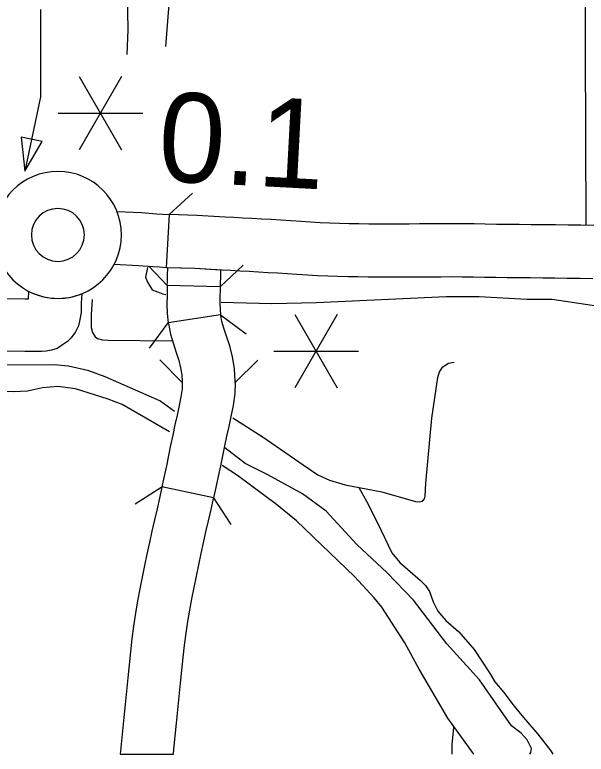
# Model space of a CAD drawing. Extents: x 1370130 to 1380143, y 377636 to 380256.
# Drawn here: x 1378668.8 to 1378782.2, y 377905.2 to 378052.1 of the extents above; entities that cross this region are included whole.
import ezdxf

# ---------------------------------------------------------------- set-up
doc = ezdxf.new("R2010")
doc.units = 0
for name, color, linetype in [('Level 10', 7, 'Continuous'), ('Level 15', 7, 'Continuous'), ('Level 24', 7, 'Continuous'), ('Level 33', 7, 'Continuous'), ('Level 34', 7, 'Continuous'), ('Level 35', 7, 'Continuous'), ('Level 37', 7, 'Continuous'), ('Level 48', 7, 'Continuous'), ('Level 6', 7, 'Continuous')]:
    doc.layers.add(name, color=color, linetype=linetype)

msp = doc.modelspace()

# ---------------------------------------------------------------- linework, layer by layer
at = {"layer": 'Level 10'}
for p, q in [((1378709.54, 377998.02), (1378699.04, 377998.3)), ((1378709.63, 377992.45), (1378699.24, 377990.91)), ((1378697.96, 377958.26), (1378697.48, 377956.09)), ((1378697.98, 377958.34), (1378697.96, 377958.26)), ((1378708.24, 377956.12), (1378697.98, 377958.34)), ((1378697.48, 377956.09), (1378697, 377953.93)), ((1378707.73, 377953.81), (1378708.22, 377956.03)), ((1378708.22, 377956.03), (1378708.24, 377956.12)), ((1378697, 377953.93), (1378696.49, 377951.75)), ((1378707.23, 377951.59), (1378707.73, 377953.81)), ((1378696.49, 377951.75), (1378695.97, 377949.51)), ((1378706.72, 377949.38), (1378707.23, 377951.59)), ((1378695.97, 377949.51), (1378695.48, 377947.24)), ((1378706.22, 377947.21), (1378706.72, 377949.38)), ((1378695.48, 377947.24), (1378695.01, 377944.97)), ((1378705.75, 377945.05), (1378706.22, 377947.21)), ((1378695.01, 377944.97), (1378694.53, 377942.7)), ((1378705.29, 377942.83), (1378705.75, 377945.05)), ((1378694.53, 377942.7), (1378694.07, 377940.41)), ((1378704.82, 377940.58), (1378705.29, 377942.83)), ((1378694.07, 377940.41), (1378693.6, 377938.07)), ((1378704.36, 377938.32), (1378704.82, 377940.58)), ((1378693.6, 377938.07), (1378693.15, 377935.67)), ((1378703.91, 377936.07), (1378704.36, 377938.32)), ((1378703.49, 377933.83), (1378703.91, 377936.07)), ((1378693.15, 377935.67), (1378692.73, 377933.21)), ((1378692.73, 377933.21), (1378692.36, 377930.68)), ((1378703.1, 377931.56), (1378703.49, 377933.83)), ((1378702.76, 377929.26), (1378703.1, 377931.56)), ((1378692.36, 377930.68), (1378692.03, 377928.11)), ((1378702.46, 377926.89), (1378702.76, 377929.26)), ((1378692.03, 377928.11), (1378691.76, 377925.54)), ((1378702.2, 377924.42), (1378702.46, 377926.89)), ((1378691.76, 377925.54), (1378691.48, 377922.97)), ((1378701.93, 377921.88), (1378702.2, 377924.42)), ((1378691.48, 377922.97), (1378691.22, 377920.36)), ((1378701.66, 377919.3), (1378701.93, 377921.88)), ((1378691.22, 377920.36), (1378690.95, 377917.74)), ((1378701.4, 377916.71), (1378701.66, 377919.3)), ((1378690.95, 377917.74), (1378690.7, 377915.1)), ((1378701.15, 377914.05), (1378701.4, 377916.71)), ((1378690.7, 377915.1), (1378690.43, 377912.5)), ((1378700.87, 377911.39), (1378701.15, 377914.05)), ((1378690.43, 377912.5), (1378690.14, 377909.87)), ((1378700.59, 377908.8), (1378700.87, 377911.39)), ((1378690.14, 377909.87), (1378689.89, 377907.24)), ((1378700.34, 377906.23), (1378700.59, 377908.8)), ((1378689.89, 377907.24), (1378689.7, 377905.22)), ((1378689.7, 377905.22), (1378700.24, 377905.22)), ((1378700.24, 377905.22), (1378700.34, 377906.23))]:
    msp.add_line(p, q, dxfattribs=at)
for points in [[(1378699.04, 377998.3), (1378699.06, 377999.07), (1378699.09, 378000.31), (1378699.13, 378001.9), (1378704.49, 378001.73)], [(1378704.49, 378001.73), (1378709.63, 378001.44), (1378709.62, 378001.15), (1378709.59, 378000.04), (1378709.56, 377998.79), (1378709.54, 377998.02)], [(1378699.04, 377998.3), (1378699.04, 377998.16), (1378699.02, 377997.74), (1378698.99, 377996.29), (1378698.96, 377994.64), (1378699.03, 377992.76), (1378699.24, 377990.91)], [(1378709.54, 377998.02), (1378709.53, 377997.83), (1378709.52, 377997.46), (1378709.48, 377996.09), (1378709.47, 377994.77), (1378709.51, 377993.55), (1378709.63, 377992.45)], [(1378712.52, 377979.03), (1378712.53, 377979.35), (1378712.35, 377981.82), (1378711.96, 377984.14), (1378711.42, 377986.29), (1378710.82, 377988.22), (1378710.27, 377989.84), (1378709.88, 377991.17), (1378709.64, 377992.37), (1378709.63, 377992.45)], [(1378699.24, 377990.91), (1378699.26, 377990.74), (1378699.68, 377988.66), (1378700.25, 377986.7), (1378700.83, 377984.97), (1378701.31, 377983.44), (1378701.68, 377981.98), (1378701.92, 377980.57), (1378702.01, 377979.18), (1378702.01, 377979.07)], [(1378702.01, 377979.07), (1378701.96, 377977.77), (1378701.74, 377976.21), (1378701.4, 377974.47), (1378700.98, 377972.58), (1378700.54, 377970.61), (1378700.11, 377968.61), (1378699.69, 377966.59), (1378699.28, 377964.56), (1378698.87, 377962.51), (1378698.42, 377960.42), (1378697.98, 377958.34)], [(1378712.51, 377979.03), (1378712.51, 377978.95), (1378712.43, 377976.84), (1378712.1, 377974.46), (1378711.67, 377972.3), (1378711.23, 377970.3), (1378710.79, 377968.37), (1378710.38, 377966.45), (1378709.98, 377964.5), (1378709.58, 377962.48), (1378709.15, 377960.38), (1378708.69, 377958.22), (1378708.24, 377956.12)]]:
    msp.add_lwpolyline(points, dxfattribs=at)
at = {"layer": 'Level 15'}
for points in [[(1378689.04, 378013.01), (1378693.93, 378012.77), (1378696.9, 378012.56), (1378699.38, 378012.4)], [(1378699.38, 378012.4), (1378698.84, 378001.91), (1378704.49, 378001.73), (1378709.96, 378001.42), (1378711.65, 378001.33), (1378713.45, 378001.21), (1378715.29, 378001.12), (1378717.14, 378001.02), (1378719.04, 378000.91), (1378720.95, 378000.8), (1378722.87, 378000.67), (1378724.84, 378000.53), (1378726.86, 378000.4), (1378728.86, 378000.3), (1378730.87, 378000.21), (1378732.87, 378000.14), (1378734.9, 378000.08), (1378736.85, 378000.06), (1378738.92, 378000.01), (1378740.96, 378000.01), (1378742.98, 378000), (1378745, 378000.01), (1378747.07, 378000.01), (1378749.2, 378000.02), (1378751.25, 378000.04), (1378753.37, 378000.05), (1378755.46, 378000.08), (1378757.58, 378000.05), (1378759.76, 378000.03), (1378761.96, 377999.98), (1378764.21, 377999.95), (1378766.49, 377999.92), (1378768.8, 377999.9), (1378771.13, 377999.88), (1378773.54, 377999.85), (1378775.94, 377999.84), (1378778.42, 377999.78), (1378780.95, 377999.76), (1378783.48, 377999.71)], [(1378783.7, 378010.21), (1378781.1, 378010.26), (1378778.59, 378010.28), (1378776.08, 378010.34), (1378773.63, 378010.35), (1378771.24, 378010.38), (1378768.88, 378010.4), (1378766.6, 378010.42), (1378764.37, 378010.44), (1378762.15, 378010.48), (1378759.92, 378010.53), (1378757.71, 378010.55), (1378755.45, 378010.58), (1378753.28, 378010.55), (1378751.16, 378010.54), (1378749.11, 378010.52), (1378747.05, 378010.51), (1378744.98, 378010.51), (1378742.99, 378010.5), (1378740.99, 378010.51), (1378739.05, 378010.51), (1378737.03, 378010.56), (1378735.1, 378010.58), (1378733.19, 378010.63), (1378731.29, 378010.7), (1378729.38, 378010.78), (1378727.47, 378010.89), (1378725.55, 378011.01), (1378723.59, 378011.15), (1378721.59, 378011.28), (1378719.64, 378011.39), (1378717.74, 378011.5), (1378715.84, 378011.61), (1378714.04, 378011.7), (1378712.26, 378011.81), (1378710.55, 378011.9), (1378704.87, 378012.22), (1378699.38, 378012.4)], [(1378688.51, 378002.53), (1378693.31, 378002.29), (1378696.16, 378002.09), (1378697.52, 378001.99), (1378698.84, 378001.91)], [(1378682.06, 377996.67), (1378681.98, 377994.81), (1378681.96, 377992.95), (1378681.7, 377991.55), (1378681.41, 377990.27), (1378680.83, 377989.11), (1378679.97, 377987.92), (1378679.23, 377987.17), (1378678.06, 377986.37), (1378677.16, 377985.81), (1378676.07, 377985.44), (1378674.98, 377985.23), (1378674.11, 377985.18), (1378670.8, 377985.18), (1378646.02, 377985.24)], [(1378646.04, 377995.74), (1378670.81, 377995.68), (1378671.51, 377995.68), (1378671.57, 377997.14), (1378672.28, 377996.8), (1378672.89, 377996.56), (1378673.48, 377996.35), (1378674.2, 377996.14), (1378674.9, 377995.98), (1378675.65, 377995.86), (1378676.17, 377995.8), (1378676.65, 377995.77), (1378677.29, 377995.75), (1378678.08, 377995.77), (1378678.75, 377995.83), (1378679.6, 377995.95), (1378680.21, 377996.08), (1378680.98, 377996.29), (1378681.58, 377996.48), (1378682.06, 377996.67)]]:
    msp.add_lwpolyline(points, dxfattribs=at)
at = {"layer": 'Level 24'}
for radius, start, end in [(12.6, 90, 270), (12.6, 270, 90), (5.25, 90, 270), (5.25, 270, 90)]:
    msp.add_arc((1378677.33, 378008.35), radius, start, end, dxfattribs=at)
at = {"layer": 'Level 33'}
for points in [[(1378684.11, 377995.52), (1378683.96, 377992.54), (1378683.96, 377989.93), (1378684.19, 377988.95), (1378684.71, 377988.08), (1378685.17, 377987.79), (1378686.15, 377987.5), (1378687.31, 377987.44), (1378700.08, 377987.3)], [(1378712.06, 377972), (1378718.05, 377968.16), (1378726.03, 377962.71), (1378728.93, 377960.71), (1378731.23, 377959.67), (1378734.31, 377958.72), (1378741.62, 377957.35), (1378748.29, 377955.4), (1378749.06, 377955.31), (1378749.69, 377955.45), (1378750.1, 377955.95), (1378750.24, 377956.45), (1378750.33, 377959.03), (1378751.51, 377971.93), (1378752.71, 377980.05), (1378753.08, 377981.19), (1378753.74, 377982.16), (1378754.83, 377982.87), (1378755.94, 377983.05)]]:
    msp.add_lwpolyline(points, dxfattribs=at)
at = {"layer": 'Level 34'}
for points in [[(1378722.09, 378115.84), (1378719.61, 378111.42), (1378716.77, 378106.31), (1378713.89, 378100.37), (1378709.84, 378092.36), (1378707.77, 378085.61), (1378706.15, 378081.91), (1378702.92, 378076.51), (1378701.12, 378071.65), (1378700.49, 378067.78), (1378699.41, 378064.18), (1378699.23, 378060.49), (1378699.5, 378057.61), (1378699.32, 378054.19), (1378698.71, 378045.76)], [(1378737.03, 377958.21), (1378738.64, 377955.36), (1378740.73, 377951.18), (1378743.63, 377945.19), (1378745.18, 377943.28), (1378749.26, 377939.74), (1378750.28, 377938.7), (1378751.1, 377937.56), (1378751.82, 377935.47), (1378752.73, 377933.61), (1378754.32, 377931.8), (1378756.91, 377929.53), (1378759.95, 377925.99), (1378762.99, 377921.4), (1378764.03, 377919.58), (1378765.84, 377917.5), (1378767.89, 377914.77), (1378769.7, 377912.5), (1378772.56, 377909.19), (1378775.15, 377905.92), (1378775.53, 377905.22)], [(1378755.55, 377905.22), (1378755.55, 377905.47), (1378755.55, 377907.14), (1378755.9, 377910.5)]]:
    msp.add_lwpolyline(points, dxfattribs=at)
at = {"layer": 'Level 35'}
for points in [[(1378716.09, 378160.72), (1378714.26, 378153.4), (1378711.72, 378145.64), (1378711.18, 378142.85), (1378711.03, 378140.16), (1378711.4, 378134.36), (1378711.92, 378129.36), (1378709.84, 378124.14), (1378710.01, 378119.81), (1378710.63, 378118.39), (1378711.15, 378115.41), (1378710.77, 378113.63), (1378709.85, 378111.22), (1378706.18, 378103.14), (1378699.13, 378084.81), (1378697.4, 378080.9), (1378695.31, 378071.81), (1378694.28, 378068.67), (1378693.34, 378067.05), (1378693, 378065.19), (1378691.74, 378061.04), (1378691.07, 378056.35), (1378691.22, 378049.07), (1378691, 378044.2)], [(1378695.13, 378001.88), (1378694.74, 377999.94), (1378695.13, 377998.97), (1378696.06, 377997.46), (1378698.18, 377996.62), (1378698.74, 377996.49)], [(1378709.72, 377994.98), (1378719.77, 377994.75), (1378728.62, 377994.94), (1378754.38, 377996.15), (1378760.96, 377996.12), (1378770.37, 377995.61), (1378775.42, 377995.59), (1378783.35, 377994.39), (1378792.75, 377993.81), (1378797.69, 377993.16), (1378803.17, 377992.06), (1378811.04, 377990.6), (1378816.89, 377989.34), (1378829.4, 377985.52), (1378832.62, 377984.71), (1378835.96, 377983.98), (1378839.26, 377983.58), (1378842.13, 377983.35), (1378844.82, 377983.4), (1378847.81, 377983.76), (1378853.13, 377985.26), (1378861.49, 377990.38)], [(1378700.47, 377973.31), (1378697.57, 377975.38), (1378686.72, 377980.16), (1378683.46, 377981.35), (1378679.43, 377982.28), (1378676.56, 377982.56), (1378663.67, 377982.45)], [(1378699.5, 377969.26), (1378690.08, 377974.67), (1378687.28, 377975.75), (1378680.83, 377977.76), (1378677.32, 377978.24), (1378674.3, 377977.96), (1378671.32, 377977.35), (1378668.5, 377977.17), (1378664.24, 377977.29), (1378653.88, 377978.75), (1378650.43, 377978.43), (1378645.42, 377976.47)], [(1378770.96, 377905.22), (1378771.18, 377905.53), (1378771.29, 377906.34), (1378770.45, 377908.09), (1378769.29, 377909.41), (1378767.32, 377910.84), (1378760.98, 377919.97), (1378754.51, 377927.16), (1378747.93, 377935.82), (1378742.64, 377941.22), (1378736.62, 377946.86), (1378730.55, 377953.47), (1378725.84, 377956.9), (1378718.98, 377960.72), (1378714.47, 377962.98), (1378710.45, 377966.09)], [(1378759.87, 377905.22), (1378754.73, 377912.39), (1378749.01, 377922.12), (1378746.21, 377927.36), (1378741.64, 377934.42), (1378740.12, 377936.28), (1378736.16, 377940.54), (1378724.69, 377951.58), (1378720.74, 377954.78), (1378712.96, 377960.59), (1378709.93, 377962.57)]]:
    msp.add_lwpolyline(points, dxfattribs=at)
at = {"layer": 'Level 37'}
for points in [[(1378699.38, 378012.4), (1378704.06, 378016.62)], [(1378699.04, 377998.3), (1378695.39, 378002.15)], [(1378714.11, 378002.36), (1378709.54, 377998.02)], [(1378709.63, 377992.45), (1378714.69, 377988.7)], [(1378695.49, 377985.85), (1378699.24, 377990.91)], [(1378702.01, 377979.07), (1378697.57, 377983.54)], [(1378716.98, 377983.47), (1378712.51, 377979.03)], [(1378692.68, 377954.94), (1378697.98, 377958.34)], [(1378708.24, 377956.12), (1378711.65, 377950.82)]]:
    msp.add_lwpolyline(points, dxfattribs=at)
at = {"layer": 'Level 48'}
for p, q in [((1378689.96, 378039.8), (1378681.56, 378025.25)), ((1378681.56, 378039.8), (1378689.96, 378025.25)), ((1378677.36, 378032.52), (1378694.16, 378032.52)), ((1378732.77, 377992.55), (1378724.37, 377978)), ((1378724.37, 377992.55), (1378732.77, 377978)), ((1378720.17, 377985.28), (1378736.97, 377985.28))]:
    msp.add_line(p, q, dxfattribs=at)
msp.add_lwpolyline([(1378673.9, 378053.13), (1378673.9, 378035.75), (1378670.78, 378021.04)], dxfattribs=at)
msp.add_lwpolyline([(1378674.21, 378026.88), (1378670.02, 378027.77), (1378670.78, 378021.04)], close=True, dxfattribs=at)
at = {"layer": 'Level 6'}
msp.add_lwpolyline([(1378681.74, 378255.37), (1378681.77, 378279.39), (1378695.52, 378278.95), (1378695.49, 378251.25), (1378684.2, 378252), (1378684.5, 378171.31), (1378670.64, 378171.33), (1378670.84, 378115.89), (1378781.72, 378115.79), (1378782.11, 378010.3)], dxfattribs=at)

# ---------------------------------------------------------------- texts
at = {"layer": 'Level 48'}
msp.add_text('0.1', height=17.741, rotation=356.9816, dxfattribs=at).set_placement((1378696.93, 378019.12))

doc.saveas('drawing.dxf')
